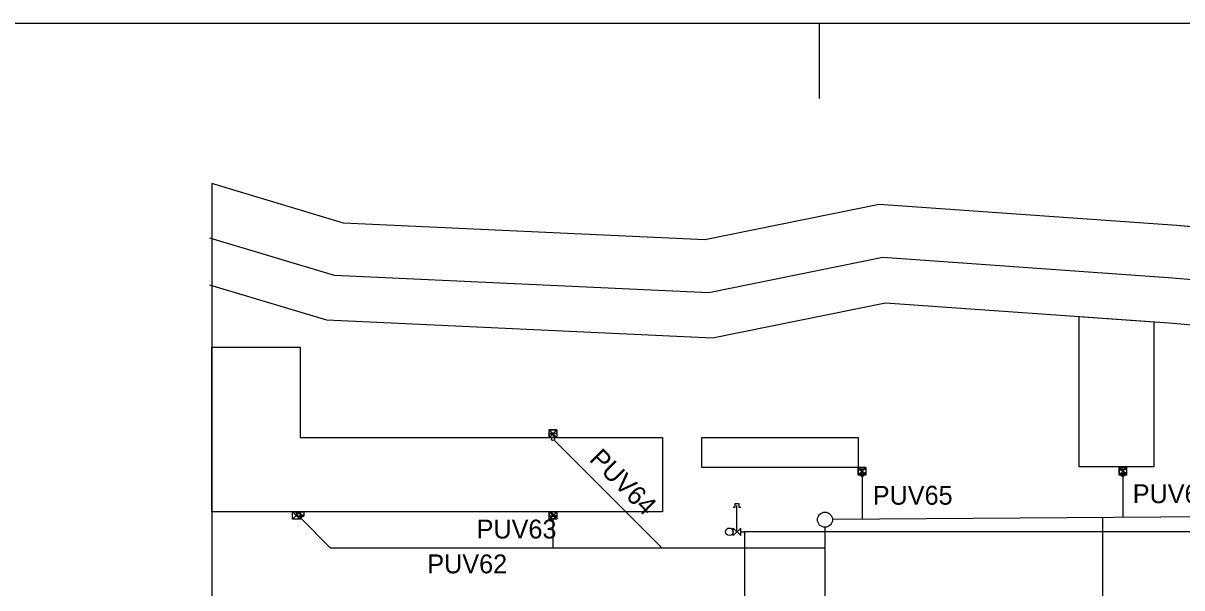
# Model space of a CAD drawing. Extents: x -264234 to -263604, y -1242346 to -1242049.
# Drawn here: x -263972 to -263895.1, y -1242086.4 to -1242048.9 of the extents above; entities that cross this region are included whole.
import ezdxf

# ---------------------------------------------------------------- set-up
doc = ezdxf.new("R2010")
doc.units = 0
for name, color, linetype in [('KFA_JESTV_IS_DSP_-_KANAL_DAZD', 7, 'Continuous'), ('KFA_SITUACIA_DSP', 7, 'Continuous'), ('KFA_SO_40-2-II_DK_PRIPOJKY_UV_PROJEKT', 7, 'Continuous'), ('KFA_SO_40-2-II_DK_PRIPOJKY_UV_PROJEKT_popis', 7, 'Continuous'), ('KFA_SO_40-2-II_DK_UV_PROJEKT', 7, 'Continuous'), ('RAM_NA_TLAC_1-500', 7, 'Continuous')]:
    doc.layers.add(name, color=color, linetype=linetype)

msp = doc.modelspace()

# ---------------------------------------------------------------- linework, layer by layer
at = {"layer": 'KFA_JESTV_IS_DSP_-_KANAL_DAZD'}
for p, q in [((-263872.456, -1242081.505), (-263918.302, -1242081.834)), ((-263918.803, -1242082.338), (-263918.855, -1242106.583))]:
    msp.add_line(p, q, dxfattribs=at)
msp.add_circle((-263918.802, -1242081.838), 0.5, dxfattribs=at)
at = {"layer": 'KFA_SITUACIA_DSP'}
for p, q in [((-263959.468, -1242059.534), (-263959.468, -1242179.482)), ((-263950.745, -1242062.149), (-263959.468, -1242059.534)), ((-263915.197, -1242060.921), (-263926.771, -1242063.254)), ((-263895.455, -1242062.322), (-263915.197, -1242060.921)), ((-263926.771, -1242063.254), (-263950.745, -1242062.149)), ((-263866.964, -1242064.823), (-263895.455, -1242062.322)), ((-263896.968, -1242068.731), (-263901.968, -1242068.376)), ((-263901.968, -1242068.376), (-263901.968, -1242074.382)), ((-263896.968, -1242074.382), (-263896.968, -1242068.731)), ((-263959.468, -1242071.382), (-263959.468, -1242070.382)), ((-263959.468, -1242070.382), (-263953.617, -1242070.382)), ((-263953.617, -1242070.382), (-263953.617, -1242076.382)), ((-263959.468, -1242076.382), (-263959.468, -1242071.382)), ((-263901.968, -1242074.382), (-263901.968, -1242078.308)), ((-263896.968, -1242078.308), (-263896.968, -1242074.382)), ((-263937.093, -1242076.382), (-263937.093, -1242076.092)), ((-263937.093, -1242076.092), (-263936.593, -1242076.092)), ((-263936.593, -1242076.382), (-263937.093, -1242076.092)), ((-263936.593, -1242076.382), (-263937.093, -1242076.092)), ((-263937.093, -1242076.092), (-263937.093, -1242076.382)), ((-263936.593, -1242076.092), (-263936.593, -1242076.382)), ((-263959.468, -1242081.307), (-263959.468, -1242076.382)), ((-263953.617, -1242076.382), (-263929.58, -1242076.382)), ((-263936.593, -1242076.382), (-263937.093, -1242076.382)), ((-263937.093, -1242076.382), (-263936.593, -1242076.382)), ((-263936.772, -1242076.553), (-263929.628, -1242083.697)), ((-263929.58, -1242076.382), (-263929.58, -1242081.307)), ((-263926.968, -1242076.382), (-263921.968, -1242076.382)), ((-263926.968, -1242078.382), (-263926.968, -1242076.382)), ((-263926.968, -1242076.382), (-263926.968, -1242076.382)), ((-263921.968, -1242076.382), (-263916.593, -1242076.382)), ((-263916.593, -1242076.382), (-263916.593, -1242078.382)), ((-263921.968, -1242078.382), (-263926.968, -1242078.382)), ((-263916.593, -1242078.382), (-263921.968, -1242078.382)), ((-263901.968, -1242078.308), (-263896.968, -1242078.308)), ((-263916.593, -1242078.777), (-263916.593, -1242078.487)), ((-263916.593, -1242078.487), (-263916.093, -1242078.487)), ((-263916.093, -1242078.777), (-263916.593, -1242078.487)), ((-263916.093, -1242078.777), (-263916.593, -1242078.487)), ((-263916.593, -1242078.487), (-263916.593, -1242078.777)), ((-263916.093, -1242078.777), (-263916.593, -1242078.777)), ((-263916.593, -1242078.777), (-263916.093, -1242078.777)), ((-263916.343, -1242078.977), (-263916.343, -1242081.82)), ((-263916.093, -1242078.487), (-263916.093, -1242078.777)), ((-263899.296, -1242078.777), (-263899.296, -1242078.487)), ((-263899.296, -1242078.487), (-263898.796, -1242078.487)), ((-263898.796, -1242078.777), (-263899.296, -1242078.487)), ((-263898.796, -1242078.777), (-263899.296, -1242078.487)), ((-263899.296, -1242078.487), (-263899.296, -1242078.777)), ((-263898.796, -1242078.777), (-263899.296, -1242078.777)), ((-263899.296, -1242078.777), (-263898.796, -1242078.777)), ((-263899.046, -1242078.977), (-263899.047, -1242081.696)), ((-263898.796, -1242078.487), (-263898.796, -1242078.777)), ((-263953.617, -1242081.307), (-263959.468, -1242081.307)), ((-263953.868, -1242081.597), (-263953.868, -1242081.307)), ((-263953.868, -1242081.307), (-263953.368, -1242081.307)), ((-263953.368, -1242081.597), (-263953.868, -1242081.307)), ((-263953.368, -1242081.597), (-263953.868, -1242081.307)), ((-263953.868, -1242081.307), (-263953.868, -1242081.597)), ((-263929.58, -1242081.307), (-263953.617, -1242081.307)), ((-263953.368, -1242081.307), (-263953.368, -1242081.597)), ((-263937.093, -1242081.597), (-263937.093, -1242081.307)), ((-263937.093, -1242081.307), (-263936.593, -1242081.307)), ((-263936.593, -1242081.597), (-263937.093, -1242081.307)), ((-263936.593, -1242081.597), (-263937.093, -1242081.307)), ((-263937.093, -1242081.307), (-263937.093, -1242081.597)), ((-263936.593, -1242081.307), (-263936.593, -1242081.597)), ((-263924.893, -1242081.015), (-263924.768, -1242081.015)), ((-263924.768, -1242081.015), (-263924.768, -1242080.765)), ((-263924.768, -1242080.765), (-263924.518, -1242080.765)), ((-263924.643, -1242082.64), (-263924.643, -1242080.89)), ((-263924.518, -1242080.765), (-263924.518, -1242081.015)), ((-263924.518, -1242081.015), (-263924.393, -1242081.015)), ((-263953.368, -1242081.597), (-263953.868, -1242081.597)), ((-263953.868, -1242081.597), (-263953.368, -1242081.597)), ((-263953.618, -1242081.697), (-263951.618, -1242083.697)), ((-263953.547, -1242081.768), (-263951.618, -1242083.697)), ((-263936.593, -1242081.597), (-263937.093, -1242081.597)), ((-263937.093, -1242081.597), (-263936.593, -1242081.597)), ((-263936.843, -1242081.797), (-263936.843, -1242083.697)), ((-263900.379, -1242090.456), (-263900.379, -1242081.705)), ((-263924.393, -1242082.39), (-263924.893, -1242082.89)), ((-263924.893, -1242082.89), (-263924.893, -1242082.39)), ((-263924.893, -1242082.39), (-263924.393, -1242082.89)), ((-263924.393, -1242082.89), (-263924.393, -1242082.39)), ((-263924.393, -1242082.64), (-263924.143, -1242082.64)), ((-263788.143, -1242082.64), (-263924.143, -1242082.64)), ((-263924.143, -1242082.64), (-263924.143, -1242185.14)), ((-263951.618, -1242083.697), (-263918.806, -1242083.697))]:
    msp.add_line(p, q, dxfattribs=at)
for points in [[(-263863.949, -1242065.106), (-263895.455, -1242062.322), (-263915.197, -1242060.921), (-263926.771, -1242063.254), (-263950.745, -1242062.149), (-263959.468, -1242059.534)], [(-263864.257, -1242068.593), (-263895.733, -1242065.811), (-263914.971, -1242064.445), (-263926.501, -1242066.77), (-263951.337, -1242065.625), (-263959.611, -1242063.145)], [(-263864.521, -1242071.581), (-263895.971, -1242068.802), (-263914.777, -1242067.467), (-263926.271, -1242069.784), (-263951.845, -1242068.605), (-263959.611, -1242066.277)]]:
    msp.add_lwpolyline(points, dxfattribs=at)
for centre, radius in [((-263936.843, -1242076.482), 0.1), ((-263916.343, -1242078.877), 0.1), ((-263899.046, -1242078.877), 0.1), ((-263953.618, -1242081.697), 0.1), ((-263936.843, -1242081.697), 0.1), ((-263925.143, -1242082.64), 0.25)]:
    msp.add_circle(centre, radius, dxfattribs=at)
at = {"layer": 'KFA_SO_40-2-II_DK_PRIPOJKY_UV_PROJEKT'}
for points in [[(-263936.772, -1242076.553), (-263929.628, -1242083.697)], [(-263916.343, -1242078.977), (-263916.343, -1242081.82)], [(-263899.046, -1242078.977), (-263899.047, -1242081.696)], [(-263953.547, -1242081.768), (-263951.618, -1242083.697), (-263918.806, -1242083.697)], [(-263936.843, -1242081.797), (-263936.843, -1242083.697)]]:
    msp.add_lwpolyline(points, dxfattribs=at)
at = {"layer": 'KFA_SO_40-2-II_DK_UV_PROJEKT'}
for points in [[(-263937.093, -1242076.382), (-263937.093, -1242075.882), (-263936.593, -1242075.882), (-263936.593, -1242076.382), (-263937.093, -1242076.382), (-263936.593, -1242075.882), (-263937.093, -1242075.882), (-263936.593, -1242076.382)], [(-263916.593, -1242078.882), (-263916.593, -1242078.382), (-263916.093, -1242078.382), (-263916.093, -1242078.882), (-263916.593, -1242078.882), (-263916.093, -1242078.382), (-263916.593, -1242078.382), (-263916.093, -1242078.882)], [(-263899.296, -1242078.882), (-263899.296, -1242078.382), (-263898.796, -1242078.382), (-263898.796, -1242078.882), (-263899.296, -1242078.882), (-263898.796, -1242078.382), (-263899.296, -1242078.382), (-263898.796, -1242078.882)], [(-263954.117, -1242081.807), (-263954.117, -1242081.307), (-263953.617, -1242081.307), (-263953.617, -1242081.807), (-263954.117, -1242081.807), (-263953.617, -1242081.307), (-263954.117, -1242081.307), (-263953.617, -1242081.807)], [(-263937.093, -1242081.807), (-263937.093, -1242081.307), (-263936.593, -1242081.307), (-263936.593, -1242081.807), (-263937.093, -1242081.807), (-263936.593, -1242081.307), (-263937.093, -1242081.307), (-263936.593, -1242081.807)]]:
    msp.add_lwpolyline(points, dxfattribs=at)
at = {"layer": 'RAM_NA_TLAC_1-500'}
msp.add_line((-263919.177, -1242048.883), (-263919.177, -1242053.883), dxfattribs=at)
msp.add_lwpolyline([(-264234.177, -1242048.883), (-263604.177, -1242048.883), (-263604.177, -1242345.883), (-264234.177, -1242345.883)], close=True, dxfattribs=at)

# ---------------------------------------------------------------- texts
at = {"layer": 'KFA_SO_40-2-II_DK_PRIPOJKY_UV_PROJEKT_popis'}
msp.add_text('PUV64', height=1.25, rotation=315, dxfattribs=at).set_placement((-263934.498, -1242077.893))
for s, p in [('PUV65', (-263915.631, -1242080.842)), ('PUV66', (-263898.385, -1242080.739)), ('PUV63', (-263941.908, -1242083.084)), ('PUV62', (-263945.18, -1242085.395))]:
    msp.add_text(s, height=1.25, dxfattribs=at).set_placement(p)

doc.saveas('drawing.dxf')
